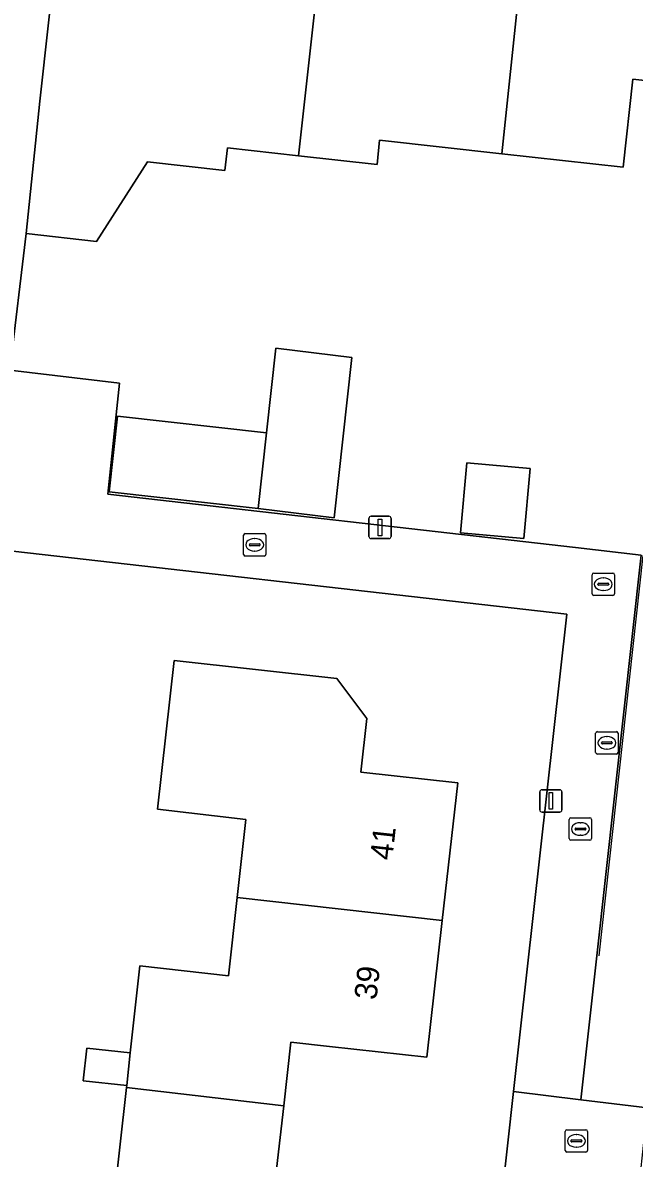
# Model space of a CAD drawing. Extents: x 162082 to 163401, y 388089 to 388636.
# Drawn here: x 162882.4 to 162909.7, y 388262 to 388312.7 of the extents above; entities that cross this region are included whole.
import ezdxf

# ---------------------------------------------------------------- set-up
doc = ezdxf.new("R2010")
doc.units = 0
for name, color, linetype in [('IMGEO_Erf', 7, 'Continuous'), ('IMGEO_Kolk', 7, 'Continuous'), ('IMGEO_Lichtmast', 7, 'Continuous'), ('IMGEO_Muur', 7, 'Continuous'), ('IMGEO_Pand', 7, 'Continuous'), ('IMGEO_Pand_nummerreeks', 7, 'Continuous'), ('IMGEO_Rioolput', 7, 'Continuous'), ('IMGEO_Voetpad_open', 7, 'Continuous')]:
    doc.layers.add(name, color=color, linetype=linetype)

msp = doc.modelspace()

# ---------------------------------------------------------------- linework, layer by layer
at = {"layer": 'IMGEO_Erf'}
for points in [[(162913.18, 388309.749), (162909.677, 388310.134), (162909.255, 388306.202), (162903.836, 388306.803), (162898.368, 388307.41), (162898.257, 388306.321), (162894.755, 388306.71), (162891.576, 388307.063), (162891.46, 388306.061), (162888.007, 388306.445), (162885.723, 388302.89), (162882.593, 388303.237), (162881.865, 388297.138), (162886.758, 388296.567), (162886.23, 388291.615), (162907.123, 388289.226), (162910.054, 388288.891), (162908.073, 388271.01), (162907.36, 388264.58), (162910.334, 388264.217)], [(162904.351, 388264.947), (162906.732, 388286.253), (162879.495, 388289.345), (162878.68, 388282.253), (162881.606, 388281.919), (162880.794, 388274.887), (162877.89, 388275.216), (162871.824, 388221.573), (162874.806, 388221.244), (162874.026, 388214.187), (162871.044, 388214.516), (162870.554, 388210.092), (162873.536, 388209.762), (162895.523, 388207.331), (162900.237, 388206.821)], [(162886.459, 388259.669), (162887.066, 388265.122), (162887.076, 388265.211), (162885.129, 388265.428), (162885.292, 388266.889), (162887.239, 388266.673), (162887.671, 388270.558), (162891.625, 388270.117), (162892.016, 388273.616), (162892.405, 388277.093), (162888.45, 388277.552), (162889.202, 388284.18), (162896.462, 388283.381), (162897.805, 388281.603), (162897.54, 388279.207), (162901.863, 388278.731), (162901.167, 388272.579), (162900.478, 388266.489), (162896.137, 388266.965), (162894.413, 388267.154), (162894.091, 388264.312), (162893.772, 388261.491)], [(162903.186, 388209.857), (162907.176, 388244.804), (162902.18, 388245.39), (162902.692, 388250), (162904.351, 388264.947)]]:
    msp.add_lwpolyline(points, dxfattribs=at)
for points in [[(162896.338, 388290.55), (162892.951, 388290.969), (162886.291, 388291.707), (162886.666, 388295.086), (162893.325, 388294.349), (162893.742, 388298.123), (162897.125, 388297.712)], [(162901.992, 388289.878), (162902.272, 388293.004), (162905.098, 388292.751), (162904.818, 388289.625)]]:
    msp.add_lwpolyline(points, close=True, dxfattribs=at)
at = {"layer": 'IMGEO_Kolk'}
for p, q in [((162892.293, 388288.924), (162892.293, 388289.776)), ((162892.368, 388289.85), (162893.22, 388289.85)), ((162893.294, 388289.776), (162893.294, 388288.924)), ((162892.552, 388289.344), (162892.552, 388289.356)), ((162892.99, 388289.307), (162892.592, 388289.307)), ((162892.595, 388289.393), (162892.993, 388289.393)), ((162892.781, 388289.63), (162892.806, 388289.63)), ((162893.036, 388289.356), (162893.036, 388289.344)), ((162893.22, 388288.85), (162892.368, 388288.85)), ((162892.804, 388289.07), (162892.779, 388289.07)), ((162907.861, 388287.164), (162907.861, 388288.016)), ((162907.936, 388288.09), (162908.788, 388288.09)), ((162908.163, 388287.633), (162908.561, 388287.633)), ((162908.349, 388287.87), (162908.374, 388287.87)), ((162908.862, 388288.016), (162908.862, 388287.164)), ((162908.12, 388287.584), (162908.12, 388287.596)), ((162908.558, 388287.547), (162908.16, 388287.547)), ((162908.372, 388287.31), (162908.347, 388287.31)), ((162908.604, 388287.596), (162908.604, 388287.584)), ((162908.788, 388287.09), (162907.936, 388287.09)), ((162906.841, 388276.24), (162906.841, 388277.092)), ((162906.916, 388277.166), (162907.768, 388277.166)), ((162907.842, 388277.092), (162907.842, 388276.24)), ((162907.1, 388276.66), (162907.1, 388276.672)), ((162907.538, 388276.623), (162907.14, 388276.623)), ((162907.143, 388276.709), (162907.541, 388276.709)), ((162907.329, 388276.946), (162907.354, 388276.946)), ((162907.584, 388276.672), (162907.584, 388276.66)), ((162907.768, 388276.166), (162906.916, 388276.166)), ((162907.352, 388276.386), (162907.327, 388276.386)), ((162906.66, 388262.318), (162906.66, 388263.17)), ((162906.735, 388263.244), (162907.587, 388263.244)), ((162906.962, 388262.787), (162907.36, 388262.787)), ((162907.148, 388263.024), (162907.173, 388263.024)), ((162907.661, 388263.17), (162907.661, 388262.318)), ((162906.919, 388262.738), (162906.919, 388262.75)), ((162907.357, 388262.701), (162906.959, 388262.701)), ((162907.171, 388262.464), (162907.146, 388262.464)), ((162907.403, 388262.75), (162907.403, 388262.738)), ((162907.587, 388262.244), (162906.735, 388262.244))]:
    msp.add_line(p, q, dxfattribs=at)
for points in [[(162892.293, 388288.924), (162892.293, 388289.776)], [(162892.368, 388289.85), (162893.22, 388289.85)], [(162893.294, 388289.776), (162893.294, 388288.924)], [(162893.22, 388288.85), (162892.368, 388288.85)], [(162907.861, 388287.164), (162907.861, 388288.016)], [(162907.936, 388288.09), (162908.788, 388288.09)], [(162908.862, 388288.016), (162908.862, 388287.164)], [(162908.788, 388287.09), (162907.936, 388287.09)], [(162906.841, 388276.24), (162906.841, 388277.092)], [(162906.916, 388277.166), (162907.768, 388277.166)], [(162907.842, 388277.092), (162907.842, 388276.24)], [(162907.768, 388276.166), (162906.916, 388276.166)], [(162906.66, 388262.318), (162906.66, 388263.17)], [(162906.735, 388263.244), (162907.587, 388263.244)], [(162907.661, 388263.17), (162907.661, 388262.318)], [(162907.587, 388262.244), (162906.735, 388262.244)]]:
    msp.add_lwpolyline(points, dxfattribs=at)
for centre, radius, start, end in [((162892.37, 388289.774), 0.0765, 91.552, 178.448), ((162892.37, 388289.774), 0.0765, 91.552, 178.448), ((162893.218, 388289.774), 0.0765, 1.552, 88.448), ((162893.218, 388289.774), 0.0765, 1.552, 88.448), ((162892.592, 388289.353), 0.0403, 85.8775, 175.7526), ((162892.589, 388289.343), 0.0366, 178.938, 274.7102), ((162892.993, 388289.35), 0.043, 264.8664, 352.4533), ((162892.997, 388289.355), 0.0386, 1.7309, 96.639), ((162892.37, 388288.926), 0.0765, 181.552, 268.448), ((162892.37, 388288.926), 0.0765, 181.552, 268.448), ((162893.218, 388288.926), 0.0765, 271.552, 358.448), ((162893.218, 388288.926), 0.0765, 271.552, 358.448), ((162907.938, 388288.014), 0.0765, 91.552, 178.448), ((162907.938, 388288.014), 0.0765, 91.552, 178.448), ((162908.16, 388287.593), 0.0403, 85.8775, 175.7526), ((162908.565, 388287.595), 0.0386, 1.7309, 96.639), ((162908.786, 388288.014), 0.0765, 1.552, 88.448), ((162908.786, 388288.014), 0.0765, 1.552, 88.448), ((162907.938, 388287.166), 0.0765, 181.552, 268.448), ((162907.938, 388287.166), 0.0765, 181.552, 268.448), ((162908.157, 388287.583), 0.0366, 178.938, 274.7102), ((162908.561, 388287.59), 0.043, 264.8664, 352.4533), ((162908.786, 388287.166), 0.0765, 271.552, 358.448), ((162908.786, 388287.166), 0.0765, 271.552, 358.448), ((162906.918, 388277.09), 0.0765, 91.552, 178.448), ((162906.918, 388277.09), 0.0765, 91.552, 178.448), ((162907.766, 388277.09), 0.0765, 1.552, 88.448), ((162907.766, 388277.09), 0.0765, 1.552, 88.448), ((162907.14, 388276.669), 0.0403, 85.8775, 175.7526), ((162907.137, 388276.659), 0.0366, 178.938, 274.7102), ((162907.541, 388276.666), 0.043, 264.8664, 352.4533), ((162907.545, 388276.671), 0.0386, 1.7309, 96.639), ((162906.918, 388276.242), 0.0765, 181.552, 268.448), ((162906.918, 388276.242), 0.0765, 181.552, 268.448), ((162907.766, 388276.242), 0.0765, 271.552, 358.448), ((162907.766, 388276.242), 0.0765, 271.552, 358.448), ((162906.737, 388263.168), 0.0765, 91.552, 178.448), ((162906.737, 388263.168), 0.0765, 91.552, 178.448), ((162906.959, 388262.747), 0.0403, 85.8775, 175.7526), ((162907.364, 388262.749), 0.0386, 1.7309, 96.639), ((162907.585, 388263.168), 0.0765, 1.552, 88.448), ((162907.585, 388263.168), 0.0765, 1.552, 88.448), ((162906.737, 388262.32), 0.0765, 181.552, 268.448), ((162906.737, 388262.32), 0.0765, 181.552, 268.448), ((162906.956, 388262.737), 0.0366, 178.938, 274.7102), ((162907.36, 388262.744), 0.043, 264.8664, 352.4533), ((162907.585, 388262.32), 0.0765, 271.552, 358.448), ((162907.585, 388262.32), 0.0765, 271.552, 358.448)]:
    msp.add_arc(centre, radius, start, end, dxfattribs=at)
for centre, major_axis, ratio, start_param, end_param in [((162892.78, 388289.35), (-0.387, 0.002), 0.722429, 4.712389, 7.853982), ((162892.805, 388289.35), (-0.39, 0.002), 0.717154, 1.570796, 4.712389), ((162908.348, 388287.59), (-0.387, 0.002), 0.722429, 4.712389, 7.853982), ((162908.373, 388287.59), (-0.39, 0.002), 0.717154, 1.570796, 4.712389), ((162907.328, 388276.666), (-0.387, 0.002), 0.722429, 4.712389, 7.853982), ((162907.353, 388276.666), (-0.39, 0.002), 0.717154, 1.570796, 4.712389), ((162907.147, 388262.744), (-0.387, 0.002), 0.722429, 4.712389, 7.853982), ((162907.172, 388262.744), (-0.39, 0.002), 0.717154, 1.570796, 4.712389)]:
    msp.add_ellipse(centre, major_axis=major_axis, ratio=ratio, start_param=start_param, end_param=end_param, dxfattribs=at)
at = {"layer": 'IMGEO_Lichtmast'}
for p, q in [((162897.895, 388289.725), (162897.895, 388290.525)), ((162897.895, 388290.525), (162897.895, 388289.725)), ((162897.995, 388290.625), (162898.785, 388290.625)), ((162898.785, 388290.625), (162897.995, 388290.625)), ((162898.885, 388290.525), (162898.885, 388289.725)), ((162898.885, 388289.725), (162898.885, 388290.525)), ((162898.785, 388289.625), (162897.995, 388289.625)), ((162897.995, 388289.625), (162898.785, 388289.625)), ((162905.527, 388277.52), (162905.527, 388278.32)), ((162905.527, 388278.32), (162905.527, 388277.52)), ((162905.627, 388278.42), (162906.417, 388278.42)), ((162906.417, 388278.42), (162905.627, 388278.42)), ((162906.517, 388278.32), (162906.517, 388277.52)), ((162906.517, 388277.52), (162906.517, 388278.32)), ((162906.417, 388277.42), (162905.627, 388277.42)), ((162905.627, 388277.42), (162906.417, 388277.42))]:
    msp.add_line(p, q, dxfattribs=at)
for points in [[(162898.315, 388290.5), (162898.465, 388290.5), (162898.465, 388289.75), (162898.315, 388289.75), (162898.315, 388290.5)], [(162905.947, 388278.295), (162906.097, 388278.295), (162906.097, 388277.545), (162905.947, 388277.545), (162905.947, 388278.295)]]:
    msp.add_lwpolyline(points, dxfattribs=at)
for centre, start, end in [((162897.995, 388290.525), 90, 180), ((162897.995, 388290.525), 90, 180), ((162898.785, 388290.525), 0, 90), ((162898.785, 388290.525), 360, 90), ((162897.995, 388289.725), 180, 270), ((162897.995, 388289.725), 180, 270), ((162898.785, 388289.725), 270, 0), ((162898.785, 388289.725), 270, 0), ((162905.627, 388278.32), 90, 180), ((162905.627, 388278.32), 90, 180), ((162906.417, 388278.32), 0, 90), ((162906.417, 388278.32), 360, 90), ((162905.627, 388277.52), 180, 270), ((162905.627, 388277.52), 180, 270), ((162906.417, 388277.52), 270, 0), ((162906.417, 388277.52), 270, 0)]:
    msp.add_arc(centre, 0.1, start, end, dxfattribs=at)
at = {"layer": 'IMGEO_Muur'}
msp.add_lwpolyline([(162908.181, 388271.003), (162910.148, 388288.869)], dxfattribs=at)
at = {"layer": 'IMGEO_Pand'}
for points in [[(162894.755, 388306.71), (162896.323, 388320.93), (162890.211, 388321.615), (162889.697, 388317.27), (162889.495, 388315.567), (162886.447, 388315.894), (162883.969, 388316.16), (162883.192, 388309.144), (162882.593, 388303.237), (162885.723, 388302.89), (162888.007, 388306.445), (162891.46, 388306.061), (162891.576, 388307.063)], [(162904.571, 388313.878), (162901.754, 388314.199), (162901.945, 388315.874), (162902.442, 388320.245), (162896.323, 388320.93), (162894.755, 388306.71), (162898.257, 388306.321), (162898.368, 388307.41), (162903.836, 388306.803)], [(162904.571, 388313.878), (162903.836, 388306.803), (162909.255, 388306.202), (162909.677, 388310.134), (162913.18, 388309.749), (162914.202, 388318.92), (162908.096, 388319.615), (162907.599, 388315.242), (162907.407, 388313.555)], [(162897.125, 388297.712), (162893.742, 388298.123), (162893.325, 388294.349), (162892.951, 388290.969), (162896.338, 388290.55)], [(162893.325, 388294.349), (162886.666, 388295.086), (162886.291, 388291.707), (162892.951, 388290.969)], [(162901.992, 388289.878), (162904.818, 388289.625), (162905.098, 388292.751), (162902.272, 388293.004)], [(162892.016, 388273.616), (162901.167, 388272.579), (162901.863, 388278.731), (162897.54, 388279.207), (162897.805, 388281.603), (162896.462, 388283.381), (162889.202, 388284.18), (162888.45, 388277.552), (162892.405, 388277.093)], [(162901.167, 388272.579), (162892.016, 388273.616), (162891.625, 388270.117), (162887.671, 388270.558), (162887.239, 388266.673), (162887.076, 388265.211), (162887.066, 388265.122), (162894.091, 388264.312), (162894.413, 388267.154), (162896.137, 388266.965), (162900.478, 388266.489)], [(162887.239, 388266.673), (162885.292, 388266.889), (162885.129, 388265.428), (162887.076, 388265.211)], [(162890.014, 388255.721), (162899.145, 388254.66), (162899.855, 388260.845), (162895.48, 388261.31), (162893.772, 388261.491), (162894.091, 388264.312), (162887.066, 388265.122), (162886.459, 388259.669), (162890.404, 388259.182)]]:
    msp.add_lwpolyline(points, close=True, dxfattribs=at)
at = {"layer": 'IMGEO_Rioolput'}
for p, q in [((162908.021, 388280.084), (162908.021, 388280.936)), ((162908.096, 388281.01), (162908.948, 388281.01)), ((162908.28, 388280.504), (162908.28, 388280.516)), ((162908.323, 388280.553), (162908.721, 388280.553)), ((162908.509, 388280.79), (162908.534, 388280.79)), ((162908.764, 388280.516), (162908.764, 388280.504)), ((162909.022, 388280.936), (162909.022, 388280.084)), ((162908.948, 388280.01), (162908.096, 388280.01)), ((162908.718, 388280.467), (162908.32, 388280.467)), ((162908.532, 388280.23), (162908.507, 388280.23))]:
    msp.add_line(p, q, dxfattribs=at)
for points in [[(162908.021, 388280.084), (162908.021, 388280.936)], [(162908.096, 388281.01), (162908.948, 388281.01)], [(162909.022, 388280.936), (162909.022, 388280.084)], [(162908.948, 388280.01), (162908.096, 388280.01)]]:
    msp.add_lwpolyline(points, dxfattribs=at)
for centre, radius, start, end in [((162908.098, 388280.934), 0.0765, 91.552, 178.448), ((162908.098, 388280.934), 0.0765, 91.552, 178.448), ((162908.32, 388280.513), 0.0403, 85.8775, 175.7526), ((162908.725, 388280.515), 0.0386, 1.7309, 96.639), ((162908.946, 388280.934), 0.0765, 1.552, 88.448), ((162908.946, 388280.934), 0.0765, 1.552, 88.448), ((162908.098, 388280.086), 0.0765, 181.552, 268.448), ((162908.098, 388280.086), 0.0765, 181.552, 268.448), ((162908.317, 388280.503), 0.0366, 178.938, 274.7102), ((162908.721, 388280.51), 0.043, 264.8664, 352.4533), ((162908.946, 388280.086), 0.0765, 271.552, 358.448), ((162908.946, 388280.086), 0.0765, 271.552, 358.448)]:
    msp.add_arc(centre, radius, start, end, dxfattribs=at)
for centre, major_axis, ratio, start_param, end_param in [((162908.508, 388280.51), (-0.387, 0.002), 0.722429, 4.712389, 7.853982), ((162908.533, 388280.51), (-0.39, 0.002), 0.717154, 1.570796, 4.712389)]:
    msp.add_ellipse(centre, major_axis=major_axis, ratio=ratio, start_param=start_param, end_param=end_param, dxfattribs=at)
at = {"layer": 'IMGEO_Voetpad_open'}
msp.add_lwpolyline([(162908.073, 388271.01), (162910.054, 388288.891), (162907.123, 388289.226), (162886.23, 388291.615), (162886.758, 388296.567), (162881.865, 388297.138), (162882.593, 388303.237), (162883.192, 388309.144), (162883.969, 388316.16), (162884.982, 388325.32), (162882.015, 388325.663), (162881.575, 388321.77), (162881.114, 388317.7), (162881.014, 388316.806), (162879.636, 388304.63), (162879.611, 388304.409), (162879.495, 388303.388), (162878.843, 388297.493), (162877.935, 388289.522), (162879.495, 388289.345), (162906.732, 388286.253), (162904.351, 388264.947), (162907.36, 388264.58)], close=True, dxfattribs=at)
msp.add_lwpolyline([(162909.814, 388259.308), (162910.334, 388264.217), (162907.36, 388264.58), (162904.351, 388264.947), (162902.692, 388250), (162902.18, 388245.39), (162907.176, 388244.804), (162903.186, 388209.857)], dxfattribs=at)

# ---------------------------------------------------------------- texts
at = {"layer": 'IMGEO_Pand_nummerreeks'}
for s, rotation, p in [('41', 83.5453, (162898.932, 388275.246)), ('39', 83.543, (162898.228, 388269.012))]:
    msp.add_text(s, height=1, rotation=rotation, dxfattribs=at).set_placement(p)

doc.saveas('drawing.dxf')
